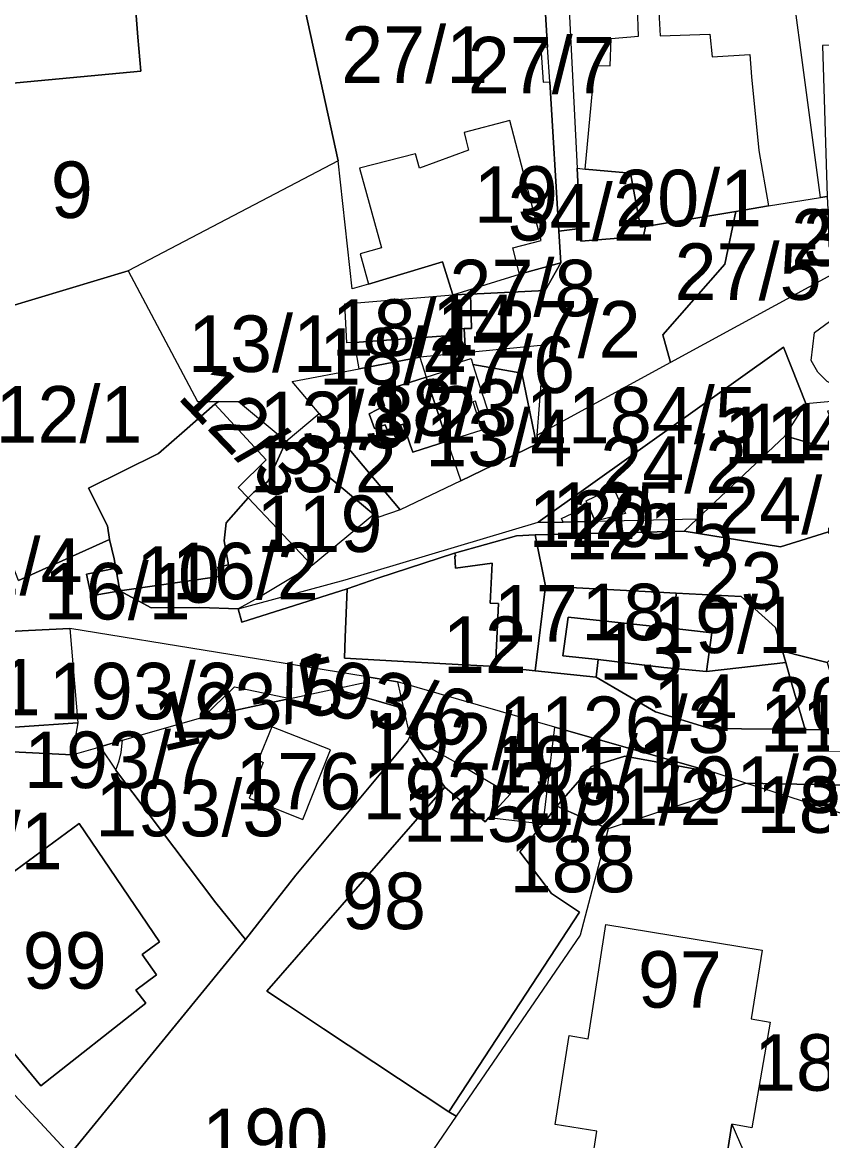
# Model space of a CAD drawing. Extents: x -623250 to -619626, y -1079612 to -1075424.
# Drawn here: x -621742.5 to -621601, y -1077535.8 to -1077337.8 of the extents above; entities that cross this region are included whole.
import ezdxf

# ---------------------------------------------------------------- set-up
doc = ezdxf.new("R2010")
doc.units = 0
for name, color, linetype in [('Hranice šetřená (k_ú_Džbánov - vnitřní obvod)', 7, 'Continuous'), ('Parcela nároku', 7, 'Continuous'), ('Parcelní číslo', 7, 'Continuous')]:
    doc.layers.add(name, color=color, linetype=linetype)

msp = doc.modelspace()

# ---------------------------------------------------------------- linework, layer by layer
at = {"layer": 'Hranice šetřená (k_ú_Džbánov - vnitřní obvod)'}
msp.add_line((-621734.05, -1077538.24), (-621752.84, -1077518.07), dxfattribs=at)
at = {"layer": 'Parcela nároku'}
for points in [[(-621600.79, -1077341.91), (-621599.98, -1077368.66), (-621601.14, -1077368.85), (-621608.91, -1077310.81), (-621614.46, -1077275.5), (-621617.74, -1077254.62), (-621618.44, -1077250.2), (-621584.31, -1077246.2), (-621576.81, -1077248.47), (-621571.17, -1077298.59), (-621567.58, -1077330.5), (-621592.44, -1077330.4), (-621592.59, -1077340.5), (-621592.59, -1077341.84)], [(-621633.38, -1077340.29), (-621633.58, -1077335.08), (-621629.83, -1077334.92), (-621629.57, -1077340.18), (-621620.76, -1077339.89), (-621620.36, -1077343.9), (-621613.65, -1077343.5), (-621613.36, -1077347.44), (-621612.06, -1077360.48), (-621610.38, -1077370.32), (-621601.14, -1077368.85), (-621608.91, -1077310.81), (-621614.46, -1077275.5), (-621648.95, -1077295.76), (-621646.56, -1077318.01), (-621644.24, -1077363.61), (-621642.81, -1077363.8), (-621641.11, -1077345.45), (-621638.39, -1077345.5), (-621638.26, -1077340.7)], [(-621722.01, -1077340.46), (-621721.53, -1077346.44), (-621750.48, -1077349.15), (-621750.65, -1077346.65), (-621758.96, -1077347.22), (-621760.22, -1077329.01), (-621760.48, -1077325.2), (-621753.9, -1077324.68), (-621754.48, -1077314.8), (-621724.25, -1077312.55), (-621723.69, -1077319.3), (-621723.35, -1077323.39)], [(-621663.9, -1077358.78), (-621663.52, -1077360.47), (-621672.18, -1077363.66), (-621672.87, -1077361.1), (-621682.78, -1077363.66), (-621678.9, -1077377.73), (-621682.67, -1077378.82), (-621681.21, -1077384.14), (-621684.1, -1077385), (-621686.57, -1077362.36), (-621694.61, -1077325.64), (-621695.25, -1077322.6), (-621650.98, -1077317.62), (-621649.48, -1077342.22), (-621650.68, -1077342.3), (-621650.3, -1077348.41), (-621649.11, -1077348.34), (-621647.49, -1077374.81), (-621647.15, -1077380.39), (-621654.46, -1077382.4), (-621655.67, -1077377.74), (-621650.61, -1077376.43), (-621656.16, -1077355.19), (-621664.28, -1077357.31)], [(-621633.58, -1077335.08), (-621629.83, -1077334.92), (-621629.57, -1077340.18), (-621620.76, -1077339.89), (-621620.36, -1077343.9), (-621613.65, -1077343.5), (-621613.36, -1077347.44), (-621612.06, -1077360.48), (-621610.38, -1077370.32), (-621616.18, -1077371.29), (-621632.17, -1077373.96), (-621633.01, -1077374.1), (-621634.82, -1077364.54), (-621642.81, -1077363.8), (-621641.11, -1077345.45), (-621638.39, -1077345.5), (-621638.26, -1077340.7), (-621633.38, -1077340.29)], [(-621649.11, -1077348.34), (-621649.48, -1077342.22), (-621650.68, -1077342.3), (-621650.3, -1077348.41)], [(-621672.87, -1077361.1), (-621682.78, -1077363.66), (-621678.9, -1077377.73), (-621682.67, -1077378.82), (-621681.21, -1077384.14), (-621668.07, -1077380.24), (-621666.27, -1077386.05), (-621654.46, -1077382.4), (-621655.67, -1077377.74), (-621650.61, -1077376.43), (-621656.16, -1077355.19), (-621664.28, -1077357.31), (-621663.9, -1077358.78), (-621663.52, -1077360.47), (-621672.18, -1077363.66)], [(-621685.05, -1077394.57), (-621685.38, -1077387.65), (-621666.27, -1077386.05), (-621668.07, -1077380.24), (-621681.21, -1077384.14), (-621684.1, -1077385), (-621686.57, -1077362.36), (-621723.75, -1077381.83), (-621711.49, -1077404.92), (-621707.69, -1077404.92), (-621704.21, -1077404.92), (-621695.78, -1077411.95), (-621689.95, -1077407.08), (-621694.73, -1077401.41), (-621682.86, -1077399.15), (-621683.68, -1077394.47)], [(-621642.81, -1077363.8), (-621634.82, -1077364.54), (-621633.01, -1077374.1), (-621632.17, -1077373.96), (-621632.5, -1077375.67), (-621643.59, -1077376.56), (-621643.7, -1077374.34), (-621644.24, -1077363.61)], [(-621601.14, -1077368.85), (-621599.98, -1077368.66), (-621599.89, -1077370.95), (-621599.68, -1077377.48), (-621593.69, -1077376.92), (-621597.29, -1077381.44), (-621627.71, -1077398.04), (-621629.08, -1077393.14), (-621618.11, -1077380.62), (-621616.18, -1077371.29), (-621610.38, -1077370.32)], [(-621649.92, -1077385.31), (-621647.15, -1077380.39), (-621647.49, -1077374.81), (-621643.7, -1077374.34), (-621643.59, -1077376.56), (-621632.5, -1077375.67), (-621632.17, -1077373.96), (-621616.18, -1077371.29), (-621618.11, -1077380.62), (-621629.08, -1077393.14), (-621627.71, -1077398.04), (-621651.31, -1077410.87), (-621650.07, -1077394.99), (-621664.03, -1077396.33), (-621664.25, -1077392.03), (-621662.95, -1077392), (-621663.16, -1077385.91)], [(-621587.33, -1077381.8), (-621565.08, -1077373.54), (-621569.08, -1077397.48), (-621570.82, -1077399.79), (-621571.73, -1077400.07), (-621582.93, -1077403.5), (-621595.64, -1077403.04), (-621597.93, -1077402.44), (-621599.99, -1077401.39), (-621601.64, -1077399.77), (-621602.8, -1077397.67), (-621602.22, -1077392.75)], [(-621654.46, -1077382.4), (-621647.15, -1077380.39), (-621649.92, -1077385.31), (-621663.16, -1077385.91), (-621666.27, -1077386.05)], [(-621727.41, -1077426.95), (-621727.07, -1077429.35), (-621743.17, -1077436.62), (-621746.17, -1077428.93), (-621748.13, -1077429.61), (-621762.23, -1077393.38), (-621723.75, -1077381.83), (-621711.49, -1077404.92), (-621707.69, -1077404.92), (-621708.4, -1077405.43), (-621713.75, -1077410.11), (-621718.37, -1077414.12), (-621730.75, -1077420.29)], [(-621666.27, -1077386.05), (-621665.97, -1077392.08), (-621665.91, -1077393.19), (-621683.68, -1077394.47), (-621685.05, -1077394.57), (-621685.38, -1077387.65)], [(-621666.27, -1077386.05), (-621663.16, -1077385.91), (-621662.95, -1077392), (-621664.25, -1077392.03), (-621665.97, -1077392.08)], [(-621664.25, -1077392.03), (-621664.03, -1077396.33), (-621672.13, -1077397.1), (-621682.86, -1077399.15), (-621683.68, -1077394.47), (-621665.91, -1077393.19), (-621665.97, -1077392.08)], [(-621665.28, -1077398.8), (-621665.5, -1077398.09), (-621663.04, -1077397.31), (-621662.7, -1077398.39), (-621654.07, -1077399.94), (-621651.44, -1077412.52), (-621651.31, -1077410.87), (-621650.07, -1077394.99), (-621664.03, -1077396.33), (-621672.13, -1077397.1), (-621671.01, -1077400.62)], [(-621603.75, -1077405.28), (-621607.7, -1077395.32), (-621651.18, -1077426.28), (-621646.74, -1077426.3), (-621647.04, -1077425.63), (-621642.26, -1077423.41), (-621642.68, -1077422.5), (-621637.87, -1077420.22), (-621635.72, -1077424.75), (-621641.09, -1077426.14), (-621623.02, -1077425.7), (-621607.45, -1077411.04)], [(-621680.11, -1077409.71), (-621678.23, -1077409.06), (-621677.92, -1077409.95), (-621677.03, -1077409.64), (-621676.48, -1077411.24), (-621675.06, -1077410.75), (-621675.62, -1077409.15), (-621675.08, -1077408.96), (-621673.83, -1077412.59), (-621673.37, -1077413.91), (-621667.27, -1077411.96), (-621664.83, -1077419.01), (-621675.57, -1077424.12), (-621689.95, -1077407.08), (-621694.73, -1077401.41), (-621682.86, -1077399.15), (-621672.13, -1077397.1), (-621671.01, -1077400.62), (-621676.7, -1077402.43), (-621676.94, -1077401.71), (-621679.42, -1077402.53), (-621678.38, -1077405.68), (-621681.09, -1077407.12)], [(-621665.5, -1077398.09), (-621663.04, -1077397.31), (-621662.7, -1077398.39), (-621661.05, -1077403.56), (-621660.78, -1077404.39), (-621660.02, -1077406.81), (-621661.48, -1077407.28), (-621662.25, -1077404.86), (-621662.73, -1077405.01), (-621661.56, -1077408.68), (-621661.14, -1077410.01), (-621667.27, -1077411.96), (-621667.71, -1077410.64), (-621671.01, -1077400.62), (-621665.28, -1077398.8)], [(-621662.25, -1077404.86), (-621662.73, -1077405.01), (-621661.56, -1077408.68), (-621661.14, -1077410.01), (-621667.27, -1077411.96), (-621664.83, -1077419.01), (-621651.44, -1077412.52), (-621654.07, -1077399.94), (-621662.7, -1077398.39), (-621661.05, -1077403.56), (-621660.78, -1077404.39), (-621660.02, -1077406.81), (-621661.48, -1077407.28)], [(-621679.42, -1077402.53), (-621676.94, -1077401.71), (-621676.7, -1077402.43), (-621671.01, -1077400.62), (-621667.71, -1077410.64), (-621667.27, -1077411.96), (-621673.37, -1077413.91), (-621673.83, -1077412.59), (-621675.08, -1077408.96), (-621675.62, -1077409.15), (-621675.06, -1077410.75), (-621676.48, -1077411.24), (-621677.03, -1077409.64), (-621677.92, -1077409.95), (-621678.23, -1077409.06), (-621680.11, -1077409.71), (-621681.09, -1077407.12), (-621678.38, -1077405.68)], [(-621607.45, -1077411.04), (-621603.75, -1077405.28), (-621591.99, -1077404.24), (-621575.61, -1077405.07), (-621599.94, -1077406.64), (-621596.63, -1077414.23)], [(-621718.37, -1077414.12), (-621713.75, -1077410.11), (-621708.4, -1077405.43), (-621699.31, -1077415.25), (-621704.29, -1077420.18), (-621702.5, -1077421.98), (-621706.4, -1077426.41), (-621706.78, -1077429.58), (-621706.01, -1077433.86), (-621707.89, -1077434.24), (-621707.61, -1077435.9), (-621725.22, -1077438.46), (-621725.95, -1077434.42), (-621726.24, -1077432.81), (-621727.07, -1077429.35), (-621727.41, -1077426.95), (-621730.75, -1077420.29)], [(-621707.69, -1077404.92), (-621704.21, -1077404.92), (-621695.78, -1077411.95), (-621699.05, -1077419.09), (-621701.52, -1077420.96), (-621702.5, -1077421.98), (-621704.29, -1077420.18), (-621699.31, -1077415.25), (-621708.4, -1077405.43)], [(-621695.78, -1077411.95), (-621689.95, -1077407.08), (-621675.57, -1077424.12), (-621679.54, -1077425.5), (-621680.23, -1077424.92)], [(-621699.05, -1077419.09), (-621695.78, -1077411.95), (-621680.23, -1077424.92), (-621691.2, -1077433.96), (-621702.5, -1077421.98), (-621701.52, -1077420.96)], [(-621623.02, -1077425.7), (-621607.45, -1077411.04), (-621596.63, -1077414.23), (-621591.86, -1077425.16), (-621590.81, -1077425.21), (-621608.27, -1077430.64), (-621625.29, -1077427.92)], [(-621642.68, -1077422.5), (-621637.87, -1077420.22), (-621635.72, -1077424.75), (-621641.09, -1077426.14), (-621642.26, -1077423.41)], [(-621706.4, -1077426.41), (-621702.5, -1077421.98), (-621691.2, -1077433.96), (-621700.64, -1077439.61), (-621704.3, -1077441.67), (-621711.05, -1077441.42), (-621719.65, -1077441.49), (-621725.22, -1077438.46), (-621707.61, -1077435.9), (-621707.89, -1077434.24), (-621706.01, -1077433.86), (-621706.78, -1077429.58)], [(-621647.04, -1077425.63), (-621642.26, -1077423.41), (-621641.09, -1077426.14), (-621646.74, -1077426.3)], [(-621685.33, -1077436.53), (-621651.18, -1077426.28), (-621646.74, -1077426.3), (-621641.09, -1077426.14), (-621623.02, -1077425.7), (-621625.29, -1077427.92), (-621651.71, -1077428.55), (-621654.98, -1077428.72), (-621665.99, -1077431.76), (-621679.57, -1077436.22), (-621684.99, -1077438.11), (-621703.6, -1077444), (-621704.3, -1077441.67)], [(-621651.71, -1077428.55), (-621625.29, -1077427.92), (-621608.27, -1077430.64), (-621590.81, -1077425.21), (-621596.41, -1077438.29), (-621595.37, -1077446.92), (-621596.41, -1077447.05), (-621596.32, -1077447.8), (-621599.98, -1077451.17), (-621607.92, -1077449.11), (-621609.14, -1077444.92), (-621615.21, -1077439.45), (-621626.72, -1077438.85), (-621649.84, -1077437.65)], [(-621665.99, -1077431.76), (-621654.98, -1077428.72), (-621651.71, -1077428.55), (-621649.84, -1077437.65), (-621651.71, -1077452.59), (-621658.72, -1077451.85), (-621658.17, -1077440.69), (-621659.64, -1077440.61), (-621659.28, -1077433.58), (-621665.81, -1077434.43), (-621665.9, -1077432.32), (-621665.74, -1077432.24)], [(-621665.81, -1077434.43), (-621659.28, -1077433.58), (-621659.64, -1077440.61), (-621658.17, -1077440.69), (-621658.72, -1077451.85), (-621667.53, -1077451.36), (-621676.07, -1077450.89), (-621685.46, -1077450.37), (-621685.32, -1077446.73), (-621684.99, -1077438.11), (-621679.57, -1077436.22), (-621665.99, -1077431.76), (-621665.74, -1077432.24), (-621665.9, -1077432.32)], [(-621731.15, -1077435.48), (-621725.95, -1077434.42), (-621725.22, -1077438.46), (-621730.3, -1077439.36)], [(-621646.76, -1077449.97), (-621640.53, -1077450.64), (-621640.86, -1077453.73), (-621651.71, -1077452.59), (-621649.84, -1077437.65), (-621626.72, -1077438.85), (-621627.07, -1077445.15), (-621645.82, -1077443.13)], [(-621609.14, -1077444.92), (-621607.92, -1077449.11), (-621607.32, -1077451.17), (-621621.36, -1077452.71), (-621620.42, -1077445.87), (-621627.07, -1077445.15), (-621626.72, -1077438.85), (-621615.21, -1077439.45)], [(-621786.37, -1077451.96), (-621748.43, -1077442.8), (-621748.07, -1077445.84), (-621755.46, -1077446.21), (-621753.4, -1077463.26), (-621732.67, -1077461.83), (-621733.65, -1077467.49), (-621762.98, -1077466.04), (-621780.8, -1077469.75)], [(-621645.82, -1077443.13), (-621627.07, -1077445.15), (-621620.42, -1077445.87), (-621621.36, -1077452.71), (-621628.89, -1077452.02), (-621640.53, -1077450.64), (-621646.76, -1077449.97)], [(-621755.46, -1077446.21), (-621748.07, -1077445.84), (-621741.37, -1077445.5), (-621734.06, -1077445.13), (-621732.67, -1077461.83), (-621753.4, -1077463.26)], [(-621681.81, -1077453.62), (-621734.06, -1077445.13), (-621732.67, -1077461.83), (-621733.65, -1077467.49), (-621728.7, -1077466.06), (-621724.76, -1077464.92), (-621710.47, -1077460.79), (-621704.94, -1077455.46), (-621695.08, -1077457.51), (-621687.07, -1077455.8), (-621681.63, -1077454.64)], [(-621607.92, -1077449.11), (-621599.98, -1077451.17), (-621596.47, -1077463.09), (-621603.87, -1077463), (-621606.45, -1077454.16), (-621607.32, -1077451.17)], [(-621640.86, -1077453.73), (-621640.53, -1077450.64), (-621628.89, -1077452.02), (-621621.36, -1077452.71), (-621607.32, -1077451.17), (-621606.45, -1077454.16), (-621603.87, -1077463), (-621620.77, -1077462.8), (-621630.41, -1077459.89)], [(-621687.07, -1077455.8), (-621681.63, -1077454.64), (-621681.81, -1077453.62), (-621676.04, -1077454.57), (-621675, -1077459.27)], [(-621687.07, -1077455.8), (-621675, -1077459.27), (-621673.89, -1077464.27), (-621674.31, -1077465.06), (-621694.06, -1077488.79), (-621703, -1077500.17), (-621708.21, -1077493.7), (-621725.47, -1077470.86), (-621725.91, -1077470.2), (-621725.33, -1077468.54), (-621724.99, -1077467.05), (-621724.76, -1077464.92), (-621710.47, -1077460.79), (-621695.08, -1077457.51)], [(-621704.94, -1077455.46), (-621695.08, -1077457.51), (-621710.47, -1077460.79)], [(-621654.35, -1077460.84), (-621676.04, -1077454.57), (-621675, -1077459.27), (-621673.89, -1077464.27), (-621663.92, -1077469.82), (-621656.1, -1077474.44)], [(-621648.21, -1077462.61), (-621654.35, -1077460.84), (-621656.1, -1077474.44), (-621659.87, -1077478.61), (-621650.29, -1077479.68)], [(-621687.93, -1077466.59), (-621698.3, -1077462.55), (-621700.76, -1077468.44), (-621699.83, -1077468.83), (-621702.34, -1077475.15), (-621692.82, -1077478.93)], [(-621700.76, -1077468.44), (-621699.83, -1077468.83), (-621702.34, -1077475.15), (-621692.82, -1077478.93), (-621687.93, -1077466.59), (-621698.3, -1077462.55)], [(-621650.29, -1077479.68), (-621648.21, -1077462.61), (-621620.02, -1077470.6), (-621635.84, -1077467.7), (-621641.71, -1077469.58), (-621647.88, -1077476.55)], [(-621708.21, -1077493.7), (-621703, -1077500.17), (-621734.05, -1077538.24), (-621752.84, -1077518.07), (-621756.42, -1077514.21), (-621787, -1077476.76), (-621790.26, -1077474.27), (-621780.8, -1077469.75), (-621762.98, -1077466.04), (-621733.65, -1077467.49), (-621728.7, -1077466.06), (-621725.91, -1077470.2), (-621725.47, -1077470.86)], [(-621689.16, -1077515.99), (-621666.98, -1077530.67), (-621665.65, -1077531.48), (-621675.33, -1077545.64), (-621680.08, -1077552.58), (-621681.9, -1077553.1), (-621688.62, -1077557.39), (-621700.52, -1077565), (-621734.05, -1077538.24), (-621703, -1077500.17), (-621694.06, -1077488.79), (-621674.31, -1077465.06), (-621673.89, -1077464.27), (-621667.71, -1077473.19), (-621699.21, -1077509.34), (-621695.56, -1077511.75)], [(-621724.76, -1077464.92), (-621728.7, -1077466.06), (-621725.91, -1077470.2), (-621725.33, -1077468.54), (-621724.99, -1077467.05)], [(-621673.89, -1077464.27), (-621663.92, -1077469.82), (-621656.1, -1077474.44), (-621659.87, -1077478.61), (-621660.54, -1077479.36), (-621667.71, -1077473.19)], [(-621635.84, -1077467.7), (-621620.02, -1077470.6), (-621619.97, -1077474.37), (-621638.79, -1077480.6), (-621647.88, -1077476.55), (-621641.71, -1077469.58)], [(-621614.41, -1077472.53), (-621620.02, -1077470.6), (-621619.97, -1077474.37)], [(-621699.21, -1077509.34), (-621667.71, -1077473.19), (-621660.54, -1077479.36), (-621659.87, -1077478.61), (-621650.29, -1077479.68), (-621654.38, -1077484.68), (-621648.79, -1077492.02), (-621643.81, -1077495.32), (-621666.98, -1077530.67), (-621689.16, -1077515.99), (-621695.56, -1077511.75)], [(-621614.41, -1077472.53), (-621569.13, -1077473.38), (-621584.71, -1077473.65), (-621588.64, -1077480.64)], [(-621650.29, -1077479.68), (-621647.88, -1077476.55), (-621638.79, -1077480.6), (-621643.71, -1077499.4), (-621665.65, -1077531.48), (-621666.98, -1077530.67), (-621643.81, -1077495.32), (-621648.79, -1077492.02), (-621654.38, -1077484.68)], [(-621722.42, -1077509.13), (-621720.63, -1077511.43), (-621739.22, -1077526.08), (-621760.51, -1077500.28), (-621732.42, -1077479.64), (-621718.2, -1077500.57), (-621721.25, -1077502.86), (-621718.73, -1077506.44)], [(-621722.42, -1077509.13), (-621718.73, -1077506.44), (-621721.25, -1077502.86), (-621718.2, -1077500.57), (-621732.42, -1077479.64), (-621760.51, -1077500.28), (-621739.22, -1077526.08), (-621720.63, -1077511.43)], [(-621643.11, -1077548.92), (-621641.26, -1077537.15), (-621640.79, -1077534.12), (-621648.14, -1077532.92), (-621645.67, -1077517.19), (-621642.32, -1077517.74), (-621639.15, -1077497.53), (-621611.52, -1077502.04), (-621613.43, -1077514.25), (-621610.05, -1077514.8), (-621613.34, -1077533.5), (-621616.86, -1077532.88), (-621618.1, -1077540.78), (-621619.61, -1077552.7)], [(-621760.82, -1077546.14), (-621757.08, -1077532.98), (-621752.84, -1077518.07), (-621734.05, -1077538.24), (-621700.52, -1077565), (-621688.62, -1077557.39), (-621707.64, -1077614.99), (-621717.4, -1077647.19), (-621727.29, -1077687.33), (-621752.14, -1077764.24), (-621804.3, -1077897.68), (-621870.37, -1077892.96), (-621848.84, -1077819.93), (-621826.8, -1077755.86), (-621795.11, -1077653.4)], [(-621625.49, -1077690.95), (-621607.09, -1077626.39), (-621598.99, -1077593.1), (-621603.38, -1077573.89), (-621608.22, -1077562.17), (-621618.1, -1077540.78), (-621616.86, -1077532.88), (-621603.65, -1077563.3), (-621599.43, -1077572.63), (-621595.47, -1077591.44), (-621604.63, -1077627.16), (-621623.5, -1077691.61), (-621629.04, -1077709.92), (-621626.22, -1077694.86)]]:
    msp.add_lwpolyline(points, close=True, dxfattribs=at)
for points in [[(-621646.56, -1077318.01), (-621644.24, -1077363.61), (-621643.7, -1077374.34), (-621647.49, -1077374.81), (-621649.11, -1077348.34), (-621649.48, -1077342.22), (-621650.98, -1077317.62)], [(-621760.22, -1077329.01), (-621758.96, -1077347.22), (-621750.65, -1077346.65), (-621750.48, -1077349.15), (-621721.53, -1077346.44), (-621722.01, -1077340.46), (-621723.35, -1077323.39)], [(-621694.61, -1077325.64), (-621686.57, -1077362.36), (-621723.75, -1077381.83), (-621762.23, -1077393.38), (-621768.84, -1077395.05), (-621775.02, -1077395.85), (-621776.13, -1077392.93), (-621783.42, -1077395.84), (-621787.9, -1077396.16), (-621784.31, -1077389.59), (-621767.57, -1077369.87), (-621767.66, -1077353.06), (-621770.15, -1077346.54), (-621770.78, -1077341.04), (-621771.66, -1077333.4)], [(-621597.29, -1077381.44), (-621627.71, -1077398.04), (-621651.31, -1077410.87), (-621651.44, -1077412.52), (-621664.83, -1077419.01), (-621675.57, -1077424.12), (-621679.54, -1077425.5), (-621680.23, -1077424.92), (-621691.2, -1077433.96), (-621700.64, -1077439.61), (-621704.3, -1077441.67), (-621685.33, -1077436.53), (-621651.18, -1077426.28), (-621607.7, -1077395.32), (-621603.75, -1077405.28), (-621591.99, -1077404.24)], [(-621599.99, -1077401.39), (-621601.64, -1077399.77), (-621602.8, -1077397.67), (-621602.22, -1077392.75), (-621587.33, -1077381.8)], [(-621743.17, -1077436.62), (-621727.07, -1077429.35), (-621726.24, -1077432.81), (-621725.95, -1077434.42), (-621731.15, -1077435.48), (-621730.3, -1077439.36), (-621725.22, -1077438.46), (-621719.65, -1077441.49), (-621711.05, -1077441.42), (-621704.3, -1077441.67), (-621703.6, -1077444), (-621684.99, -1077438.11), (-621685.32, -1077446.73), (-621685.46, -1077450.37), (-621676.07, -1077450.89), (-621667.53, -1077451.36), (-621658.72, -1077451.85), (-621651.71, -1077452.59), (-621640.86, -1077453.73), (-621630.41, -1077459.89), (-621620.77, -1077462.8), (-621603.87, -1077463), (-621596.47, -1077463.09)], [(-621569.13, -1077473.38), (-621614.41, -1077472.53), (-621620.02, -1077470.6), (-621648.21, -1077462.61), (-621654.35, -1077460.84), (-621676.04, -1077454.57), (-621681.81, -1077453.62), (-621734.06, -1077445.13), (-621741.37, -1077445.5), (-621748.07, -1077445.84)], [(-621585.75, -1077543.14), (-621569.52, -1077504.32), (-621590.99, -1077492.25), (-621588.64, -1077480.64), (-621614.41, -1077472.53), (-621619.97, -1077474.37), (-621638.79, -1077480.6), (-621643.71, -1077499.4), (-621665.65, -1077531.48), (-621675.33, -1077545.64)], [(-621641.26, -1077537.15), (-621640.79, -1077534.12), (-621648.14, -1077532.92), (-621645.67, -1077517.19), (-621642.32, -1077517.74), (-621639.15, -1077497.53), (-621611.52, -1077502.04), (-621613.43, -1077514.25), (-621610.05, -1077514.8), (-621613.34, -1077533.5), (-621616.86, -1077532.88), (-621603.65, -1077563.3)]]:
    msp.add_lwpolyline(points, dxfattribs=at)

# ---------------------------------------------------------------- texts
at = {"layer": 'Parcelní číslo'}
for s, p in [('27/1', (-621686.04, -1077348.54)), ('27/7', (-621663.62, -1077350.39)), ('9', (-621737.45, -1077372.45)), ('19', (-621662.55, -1077373.3)), ('20/1', (-621637.52, -1077373.92)), ('34/2', (-621656.54, -1077376.44)), ('27/4', (-621606.37, -1077380.87)), ('37', (-621604.22, -1077380.95)), ('27/5', (-621627, -1077386.94)), ('27/8', (-621666.87, -1077389.85)), ('18/1', (-621687.73, -1077396.85)), ('14', (-621669.92, -1077396.04)), ('27/2', (-621659.04, -1077397.16)), ('13/1', (-621713.16, -1077399.71)), ('18/4', (-621689.95, -1077401.96)), ('27/6', (-621670.65, -1077403.42)), ('18/3', (-621680.9, -1077411.01)), ('12/1', (-621747.24, -1077412.21)), ('13/3', (-621700.49, -1077413.2)), ('18/2', (-621688.02, -1077412.23)), ('1184/5', (-621653.34, -1077412.36)), ('13/4', (-621671.13, -1077416.39)), ('1148/1', (-621618.24, -1077415.86)), ('1148/2', (-621615.07, -1077415.34)), ('13/2', (-621702.22, -1077421.01)), ('24/2', (-621640.17, -1077421.12)), ('24/1', (-621619.44, -1077428.36)), ('120', (-621652.84, -1077430.67)), ('125', (-621648.69, -1077429.26)), ('119', (-621701.03, -1077431.58)), ('1215', (-621646.37, -1077432.87)), ('12/4', (-621757.86, -1077439.14)), ('10', (-621722.37, -1077440.56)), ('16/2', (-621716.03, -1077439.95)), ('23', (-621622.73, -1077441.63)), ('16/1', (-621738.7, -1077443.52)), ('17', (-621659.01, -1077447.44)), ('18', (-621643.53, -1077447.19)), ('19/1', (-621630.82, -1077449.47)), ('12', (-621668.03, -1077452.99)), ('13', (-621640.38, -1077454.17)), ('11', (-621754.1, -1077460.51)), ('193/2', (-621737.8, -1077461.2)), ('14', (-621630.81, -1077463.24)), ('20', (-621610.41, -1077463.75)), ('1126/3', (-621658.15, -1077467.16)), ('1150/1', (-621611.91, -1077466.9)), ('192/1', (-621681.73, -1077470.1)), ('193/7', (-621742.19, -1077473.37)), ('191/1', (-621659.54, -1077474.16)), ('176', (-621704.79, -1077477.16)), ('191/3', (-621631, -1077477.77)), ('192/2', (-621682.27, -1077478.91)), ('191/2', (-621652.16, -1077479.9)), ('193/3', (-621729.55, -1077481.92)), ('185/2', (-621612.47, -1077481.3)), ('1150/2', (-621675.13, -1077482.88)), ('193/1', (-621768.82, -1077487.74)), ('188', (-621656.22, -1077491.82)), ('98', (-621685.9, -1077498.34)), ('99', (-621742.42, -1077508.89)), ('97', (-621633.49, -1077512.25)), ('185/1', (-621612.95, -1077526.95)), ('190', (-621710.64, -1077540.11))]:
    msp.add_text(s, height=10, dxfattribs=at).set_placement(p)
for s, rotation, p in [('12/3', 313.9659, (-621715.27, -1077404.23)), ('193/5', 12.7568, (-621717.67, -1077466.96)), ('193/6', 346.0671, (-621696.34, -1077458.35))]:
    msp.add_text(s, height=10, rotation=rotation, dxfattribs=at).set_placement(p)

doc.saveas('drawing.dxf')
